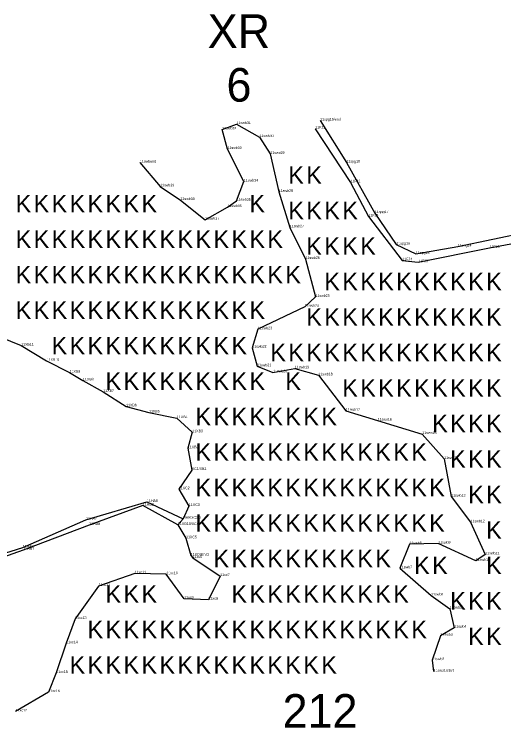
# Model space of a CAD drawing. Extents: x 2072529 to 2268812, y 436423 to 470008.
# Drawn here: x 2230174 to 2231127, y 446771 to 448159 of the extents above; entities that cross this region are included whole.
import ezdxf

# ---------------------------------------------------------------- set-up
doc = ezdxf.new("R2010")
doc.units = 0
for name, color, linetype in [('Old_Level_10', 7, 'Continuous'), ('Old_Level_20', 7, 'Continuous'), ('Old_Level_52', 7, 'Continuous'), ('Old_Level_55', 7, 'Continuous'), ('Old_Level_60', 7, 'Continuous'), ('Old_Level_62', 7, 'Continuous')]:
    doc.layers.add(name, color=color, linetype=linetype)

msp = doc.modelspace()

# ---------------------------------------------------------------- linework, layer by layer
at = {"layer": 'Old_Level_10'}
for points in [[(2230769.394, 447951.882), (2230820.468, 447870.14), (2230875.802, 447771.916), (2230917.643, 447710.638), (2230955.8, 447692.492), (2231037.496, 447706.907), (2231173.407, 447735.498), (2231315.304, 447761.122), (2231455.152, 447786.77), (2231613.245, 447790.272), (2231730.779, 447794.105), (2231802.313, 447822.04), (2231902.637, 447895.433), (2231968.706, 447942.06), (2232060.909, 448002.163), (2232107.899, 448039.336), (2232157.408, 448074.653), (2232140.017, 448092.714), (2232118.49, 448126.789)], [(2230418.674, 447870.165), (2230457.785, 447823.781), (2230497.454, 447797.32), (2230545.291, 447758.924), (2230589.102, 447783.547), (2230606.663, 447795.911), (2230620.955, 447833.276), (2230589.052, 447896.493), (2230578.639, 447934.458), (2230606.793, 447944.95), (2230651.122, 447919.651), (2230672.44, 447886.991), (2230688.884, 447813.012), (2230710.238, 447744.027), (2230740.968, 447682.572), (2230760.414, 447609.03), (2230739.307, 447589.655), (2230648.264, 447546.025), (2230637.297, 447510.087), (2230646.632, 447474.103), (2230677.584, 447462.11), (2230720.249, 447469.884), (2230766.042, 447456.434), (2230819.357, 447387.419), (2230881.339, 447368.316), (2230968.283, 447342.148), (2231010.924, 447293.767), (2231024.565, 447220.494), (2231062.235, 447170.609), (2231090.759, 447108.107), (2231072.339, 447095.635), (2230999.24, 447129.252), (2230943.038, 447127.924), (2230924.582, 447081.203), (2230985.35, 447028.279), (2231021.52, 447002.6), (2231030.311, 446965.581), (2231003.625, 446949.889), (2230987.319, 446902.522), (2230990.319, 446880.292)]]:
    msp.add_lwpolyline(points, dxfattribs=at)
at = {"layer": 'Old_Level_20'}
for p, q in [((2230606.793, 447944.95), (2230606.793, 447944.95)), ((2230769.394, 447951.882), (2230769.394, 447951.882)), ((2230769.394, 447951.882), (2230769.394, 447951.882)), ((2230578.639, 447934.458), (2230578.639, 447934.458)), ((2230759.811, 447936.011), (2230759.811, 447936.011)), ((2230651.122, 447919.651), (2230651.122, 447919.651)), ((2230589.052, 447896.493), (2230589.052, 447896.493)), ((2230672.44, 447886.991), (2230672.44, 447886.991)), ((2230418.674, 447870.165), (2230418.674, 447870.165)), ((2230820.468, 447870.14), (2230820.468, 447870.14)), ((2230820.468, 447870.14), (2230820.468, 447870.14)), ((2230620.955, 447833.276), (2230620.955, 447833.276)), ((2230828.534, 447831.652), (2230828.534, 447831.652)), ((2230457.785, 447823.781), (2230457.785, 447823.781)), ((2230688.884, 447813.012), (2230688.884, 447813.012)), ((2230497.454, 447797.32), (2230497.454, 447797.32)), ((2230606.663, 447795.911), (2230606.663, 447795.911)), ((2230589.102, 447783.547), (2230589.102, 447783.547)), ((2230863.533, 447765.149), (2230863.533, 447765.149)), ((2230875.802, 447771.916), (2230875.802, 447771.916)), ((2230875.802, 447771.916), (2230875.802, 447771.916)), ((2230545.291, 447758.924), (2230545.291, 447758.924)), ((2230710.238, 447744.027), (2230710.238, 447744.027)), ((2230917.643, 447710.638), (2230917.643, 447710.638)), ((2230917.643, 447710.638), (2230917.643, 447710.638)), ((2231037.496, 447706.907), (2231037.496, 447706.907)), ((2231037.496, 447706.907), (2231037.496, 447706.907)), ((2231099.106, 447704.027), (2231099.106, 447704.027)), ((2230955.8, 447692.492), (2230955.8, 447692.492)), ((2230955.8, 447692.492), (2230955.8, 447692.492)), ((2230740.968, 447682.572), (2230740.968, 447682.572)), ((2230929.3, 447679.936), (2230929.3, 447679.936)), ((2230960.246, 447676.326), (2230960.246, 447676.326)), ((2230760.414, 447609.03), (2230760.414, 447609.03)), ((2230739.307, 447589.655), (2230739.307, 447589.655)), ((2230648.264, 447546.025), (2230648.264, 447546.025)), ((2230187.479, 447514.119), (2230187.479, 447514.119)), ((2230637.297, 447510.087), (2230637.297, 447510.087)), ((2230236.995, 447484.617), (2230236.995, 447484.617)), ((2230646.632, 447474.103), (2230646.632, 447474.103)), ((2230720.249, 447469.884), (2230720.249, 447469.884)), ((2230281.831, 447461.598), (2230281.831, 447461.598)), ((2230677.584, 447462.11), (2230677.584, 447462.11)), ((2230766.042, 447456.434), (2230766.042, 447456.434)), ((2230307.705, 447446.476), (2230307.705, 447446.476)), ((2230347.244, 447424.166), (2230347.244, 447424.166)), ((2230391.645, 447396.034), (2230391.645, 447396.034)), ((2230819.357, 447387.419), (2230819.357, 447387.419)), ((2230436.28, 447384.089), (2230436.28, 447384.089)), ((2230490.653, 447373.166), (2230490.653, 447373.166)), ((2230881.339, 447368.316), (2230881.339, 447368.316)), ((2230520.496, 447345.748), (2230520.496, 447345.748)), ((2230968.283, 447342.148), (2230968.283, 447342.148)), ((2230511.824, 447314.745), (2230511.824, 447314.745)), ((2231010.924, 447293.767), (2231010.924, 447293.767)), ((2230519.567, 447272.202), (2230519.567, 447272.202)), ((2230494.218, 447234.889), (2230494.218, 447234.889)), ((2231024.565, 447220.494), (2231024.565, 447220.494)), ((2230432.311, 447210.178), (2230432.311, 447210.178)), ((2230424.391, 447203.105), (2230424.391, 447203.105)), ((2230513.948, 447202.276), (2230513.948, 447202.276)), ((2230502.832, 447177.345), (2230502.832, 447177.345)), ((2230313.663, 447175.511), (2230313.663, 447175.511)), ((2230319.6, 447165.281), (2230319.6, 447165.281)), ((2230492.588, 447165.355), (2230492.588, 447165.355)), ((2231062.235, 447170.609), (2231062.235, 447170.609)), ((2230508.296, 447139.437), (2230508.296, 447139.437)), ((2230190.395, 447121.729), (2230190.395, 447121.729)), ((2230943.038, 447127.924), (2230943.038, 447127.924)), ((2230999.24, 447129.252), (2230999.24, 447129.252)), ((2230191.644, 447116.47), (2230191.644, 447116.47)), ((2231090.759, 447108.107), (2231090.759, 447108.107)), ((2230517.415, 447105.795), (2230517.415, 447105.795)), ((2230521.647, 447101.442), (2230521.647, 447101.442)), ((2231072.339, 447095.635), (2231072.339, 447095.635)), ((2230924.582, 447081.203), (2230924.582, 447081.203)), ((2230408.408, 447071.303), (2230408.408, 447071.303)), ((2230469.973, 447069.696), (2230469.973, 447069.696)), ((2230574.736, 447066.064), (2230574.736, 447066.064)), ((2230338.319, 447046.586), (2230338.319, 447046.586)), ((2230985.35, 447028.279), (2230985.35, 447028.279)), ((2230504.663, 447022.064), (2230504.663, 447022.064)), ((2230551.941, 447020.098), (2230551.941, 447020.098)), ((2231021.52, 447002.6), (2231021.52, 447002.6)), ((2230292.282, 446982.862), (2230292.282, 446982.862)), ((2231030.311, 446965.581), (2231030.311, 446965.581)), ((2231003.625, 446949.889), (2231003.625, 446949.889)), ((2230275.143, 446935.245), (2230275.143, 446935.245)), ((2230987.319, 446902.522), (2230987.319, 446902.522)), ((2230255.83, 446877.586), (2230255.83, 446877.586)), ((2230990.319, 446880.292), (2230990.319, 446880.292)), ((2230240.469, 446840.352), (2230240.469, 446840.352)), ((2230176.496, 446802.681), (2230176.496, 446802.681))]:
    msp.add_line(p, q, dxfattribs=at)
at = {"layer": 'Old_Level_52'}
for points in [[(2230759.811, 447936.011), (2230828.534, 447831.652), (2230863.533, 447765.149), (2230929.3, 447679.936), (2230960.246, 447676.326), (2231099.106, 447704.027), (2231237.511, 447730.295), (2231391.369, 447760.081), (2231546.1, 447771.484), (2231706.131, 447772.616), (2231807.646, 447794.925), (2231974.226, 447918.42)], [(2230145.048, 447531.311), (2230187.479, 447514.119), (2230236.995, 447484.617), (2230281.831, 447461.598), (2230307.705, 447446.476), (2230347.244, 447424.166), (2230391.645, 447396.034), (2230436.28, 447384.089), (2230490.653, 447373.166), (2230520.496, 447345.748), (2230511.824, 447314.745), (2230519.567, 447272.202), (2230494.218, 447234.889), (2230513.948, 447202.276), (2230502.832, 447177.345), (2230492.588, 447165.355), (2230508.296, 447139.437), (2230517.415, 447105.795)], [(2230492.588, 447165.355), (2230424.391, 447203.105), (2230319.6, 447165.281), (2230191.644, 447116.47), (2230068.223, 447073.263), (2229915.312, 447016.898), (2229787.07, 446977.903), (2229665.632, 446932.019), (2229590.567, 446934.149), (2229593.53, 446943.669), (2229665.094, 446950.354), (2229787.213, 446986.774), (2229909.621, 447029.326), (2230066.407, 447082.621), (2230190.395, 447121.729), (2230313.663, 447175.511), (2230432.311, 447210.178), (2230502.832, 447177.345)], [(2230517.415, 447105.795), (2230521.647, 447101.442), (2230574.736, 447066.064), (2230551.941, 447020.098), (2230504.663, 447022.064), (2230469.973, 447069.696), (2230408.408, 447071.303), (2230338.319, 447046.586), (2230292.282, 446982.862), (2230275.143, 446935.245), (2230255.83, 446877.586), (2230240.469, 446840.352), (2230176.496, 446802.681)]]:
    msp.add_lwpolyline(points, dxfattribs=at)

# ---------------------------------------------------------------- texts
at = {"layer": 'Old_Level_55'}
for p in [(2230707.479, 447828.791), (2230742.479, 447828.791), (2230176.739, 447773.184), (2230211.739, 447773.184), (2230246.739, 447773.184), (2230281.739, 447773.184), (2230316.739, 447773.184), (2230351.739, 447773.184), (2230386.739, 447773.184), (2230421.739, 447773.184), (2230631.739, 447773.184), (2230707.479, 447759.791), (2230742.479, 447759.791), (2230777.479, 447759.791), (2230812.479, 447759.791), (2230176.739, 447704.184), (2230211.739, 447704.184), (2230246.739, 447704.184), (2230281.739, 447704.184), (2230316.739, 447704.184), (2230351.739, 447704.184), (2230386.739, 447704.184), (2230421.739, 447704.184), (2230456.739, 447704.184), (2230491.739, 447704.184), (2230526.739, 447704.184), (2230561.739, 447704.184), (2230596.739, 447704.184), (2230631.739, 447704.184), (2230666.739, 447704.184), (2230742.479, 447690.791), (2230777.479, 447690.791), (2230812.479, 447690.791), (2230847.479, 447690.791), (2230176.739, 447635.184), (2230211.739, 447635.184), (2230246.739, 447635.184), (2230281.739, 447635.184), (2230316.739, 447635.184), (2230351.739, 447635.184), (2230386.739, 447635.184), (2230421.739, 447635.184), (2230456.739, 447635.184), (2230491.739, 447635.184), (2230526.739, 447635.184), (2230561.739, 447635.184), (2230596.739, 447635.184), (2230631.739, 447635.184), (2230666.739, 447635.184), (2230701.739, 447635.184), (2230777.479, 447621.791), (2230812.479, 447621.791), (2230847.479, 447621.791), (2230882.479, 447621.791), (2230917.479, 447621.791), (2230952.479, 447621.791), (2230987.479, 447621.791), (2231022.479, 447621.791), (2231057.479, 447621.791), (2231092.479, 447621.791), (2230176.739, 447566.184), (2230211.739, 447566.184), (2230246.739, 447566.184), (2230281.739, 447566.184), (2230316.739, 447566.184), (2230351.739, 447566.184), (2230386.739, 447566.184), (2230421.739, 447566.184), (2230456.739, 447566.184), (2230491.739, 447566.184), (2230526.739, 447566.184), (2230561.739, 447566.184), (2230596.739, 447566.184), (2230631.739, 447566.184), (2230742.479, 447552.791), (2230777.479, 447552.791), (2230812.479, 447552.791), (2230847.479, 447552.791), (2230882.479, 447552.791), (2230917.479, 447552.791), (2230952.479, 447552.791), (2230987.479, 447552.791), (2231022.479, 447552.791), (2231057.479, 447552.791), (2231092.479, 447552.791), (2230246.739, 447497.184), (2230281.739, 447497.184), (2230316.739, 447497.184), (2230351.739, 447497.184), (2230386.739, 447497.184), (2230421.739, 447497.184), (2230456.739, 447497.184), (2230491.739, 447497.184), (2230526.739, 447497.184), (2230561.739, 447497.184), (2230596.739, 447497.184), (2230672.479, 447483.791), (2230707.479, 447483.791), (2230742.479, 447483.791), (2230777.479, 447483.791), (2230812.479, 447483.791), (2230847.479, 447483.791), (2230882.479, 447483.791), (2230917.479, 447483.791), (2230952.479, 447483.791), (2230987.479, 447483.791), (2231022.479, 447483.791), (2231057.479, 447483.791), (2231092.479, 447483.791), (2230351.739, 447428.184), (2230386.739, 447428.184), (2230421.739, 447428.184), (2230456.739, 447428.184), (2230491.739, 447428.184), (2230526.739, 447428.184), (2230561.739, 447428.184), (2230596.739, 447428.184), (2230631.739, 447428.184), (2230701.739, 447428.184), (2230812.479, 447414.791), (2230847.479, 447414.791), (2230882.479, 447414.791), (2230917.479, 447414.791), (2230952.479, 447414.791), (2230987.479, 447414.791), (2231022.479, 447414.791), (2231057.479, 447414.791), (2231092.479, 447414.791), (2230526.739, 447359.184), (2230561.739, 447359.184), (2230596.739, 447359.184), (2230631.739, 447359.184), (2230666.739, 447359.184), (2230701.739, 447359.184), (2230736.739, 447359.184), (2230771.739, 447359.184), (2230987.479, 447345.791), (2231022.479, 447345.791), (2231057.479, 447345.791), (2231092.479, 447345.791), (2230526.739, 447290.184), (2230561.739, 447290.184), (2230596.739, 447290.184), (2230631.739, 447290.184), (2230666.739, 447290.184), (2230701.739, 447290.184), (2230736.739, 447290.184), (2230771.739, 447290.184), (2230806.739, 447290.184), (2230841.739, 447290.184), (2230876.739, 447290.184), (2230911.739, 447290.184), (2230946.739, 447290.184), (2231022.479, 447276.791), (2231057.479, 447276.791), (2231092.479, 447276.791), (2230526.739, 447221.184), (2230561.739, 447221.184), (2230596.739, 447221.184), (2230631.739, 447221.184), (2230666.739, 447221.184), (2230701.739, 447221.184), (2230736.739, 447221.184), (2230771.739, 447221.184), (2230806.739, 447221.184), (2230841.739, 447221.184), (2230876.739, 447221.184), (2230911.739, 447221.184), (2230946.739, 447221.184), (2230981.739, 447221.184), (2231057.479, 447207.791), (2231092.479, 447207.791), (2230526.739, 447152.184), (2230561.739, 447152.184), (2230596.739, 447152.184), (2230631.739, 447152.184), (2230666.739, 447152.184), (2230701.739, 447152.184), (2230736.739, 447152.184), (2230771.739, 447152.184), (2230806.739, 447152.184), (2230841.739, 447152.184), (2230876.739, 447152.184), (2230911.739, 447152.184), (2230946.739, 447152.184), (2230981.739, 447152.184), (2231092.479, 447138.791), (2230561.739, 447083.184), (2230596.739, 447083.184), (2230631.739, 447083.184), (2230666.739, 447083.184), (2230701.739, 447083.184), (2230736.739, 447083.184), (2230771.739, 447083.184), (2230806.739, 447083.184), (2230841.739, 447083.184), (2230876.739, 447083.184), (2230952.479, 447069.791), (2230987.479, 447069.791), (2231092.479, 447069.791), (2230351.739, 447014.184), (2230386.739, 447014.184), (2230421.739, 447014.184), (2230596.739, 447014.184), (2230631.739, 447014.184), (2230666.739, 447014.184), (2230701.739, 447014.184), (2230736.739, 447014.184), (2230771.739, 447014.184), (2230806.739, 447014.184), (2230841.739, 447014.184), (2230876.739, 447014.184), (2230911.739, 447014.184), (2231022.479, 447000.791), (2231057.479, 447000.791), (2231092.479, 447000.791), (2230316.739, 446945.184), (2230351.739, 446945.184), (2230386.739, 446945.184), (2230421.739, 446945.184), (2230456.739, 446945.184), (2230491.739, 446945.184), (2230526.739, 446945.184), (2230561.739, 446945.184), (2230596.739, 446945.184), (2230631.739, 446945.184), (2230666.739, 446945.184), (2230701.739, 446945.184), (2230736.739, 446945.184), (2230771.739, 446945.184), (2230806.739, 446945.184), (2230841.739, 446945.184), (2230876.739, 446945.184), (2230911.739, 446945.184), (2230946.739, 446945.184), (2231057.479, 446931.791), (2231092.479, 446931.791), (2230281.739, 446876.184), (2230316.739, 446876.184), (2230351.739, 446876.184), (2230386.739, 446876.184), (2230421.739, 446876.184), (2230456.739, 446876.184), (2230491.739, 446876.184), (2230526.739, 446876.184), (2230561.739, 446876.184), (2230596.739, 446876.184), (2230631.739, 446876.184), (2230666.739, 446876.184), (2230701.739, 446876.184), (2230736.739, 446876.184), (2230771.739, 446876.184)]:
    msp.add_text('K', height=34, dxfattribs=at).set_placement(p)
at = {"layer": 'Old_Level_60'}
for s, p in [('11spg19/end', (2230769.394, 447951.882)), ('11spg19/end', (2230769.394, 447951.882)), ('11swb31', (2230606.793, 447944.95)), ('11FJ1', (2230759.811, 447936.011)), ('11swb32', (2230578.639, 447934.458)), ('11swb30', (2230651.122, 447919.651)), ('11swb33', (2230589.052, 447896.493)), ('11swb29', (2230672.44, 447886.991)), ('11swbend', (2230418.674, 447870.165)), ('11spg18', (2230820.468, 447870.14)), ('11spg18', (2230820.468, 447870.14)), ('11swb39', (2230457.785, 447823.781)), ('11swb34', (2230620.955, 447833.276)), ('11FJ2', (2230828.534, 447831.652)), ('11swb28', (2230688.884, 447813.012)), ('11swb38', (2230497.454, 447797.32)), ('11swb35', (2230606.663, 447795.911)), ('11swb36', (2230589.102, 447783.547)), ('11spg17', (2230875.802, 447771.916)), ('11spg17', (2230875.802, 447771.916)), ('11swb37', (2230545.291, 447758.924)), ('11FJ3', (2230863.533, 447765.149)), ('11swb27', (2230710.238, 447744.027)), ('11spg16', (2230917.643, 447710.638)), ('11spg16', (2230917.643, 447710.638)), ('11spg14', (2231037.496, 447706.907)), ('11spg14', (2231037.496, 447706.907)), ('11FJ6', (2231099.106, 447704.027)), ('11spg15', (2230955.8, 447692.492)), ('11spg15', (2230955.8, 447692.492)), ('11swb26', (2230740.968, 447682.572)), ('11FJ4', (2230929.3, 447679.936)), ('11FJ5', (2230960.246, 447676.326)), ('11swb25', (2230760.414, 447609.03)), ('11swb24', (2230739.307, 447589.655)), ('11swb23', (2230648.264, 447546.025)), ('11XB11', (2230187.479, 447514.119)), ('11swb22', (2230637.297, 447510.087)), ('11XB10', (2230236.995, 447484.617)), ('11swb21', (2230646.632, 447474.103)), ('11swb19', (2230720.249, 447469.884)), ('11XB9', (2230281.831, 447461.598)), ('11swb20', (2230677.584, 447462.11)), ('11swb18', (2230766.042, 447456.434)), ('11XB8', (2230307.705, 447446.476)), ('11XB7', (2230347.244, 447424.166)), ('11XB6', (2230391.645, 447396.034)), ('11XB5', (2230436.28, 447384.089)), ('11swb17', (2230819.357, 447387.419)), ('11XB4', (2230490.653, 447373.166)), ('11swb16', (2230881.339, 447368.316)), ('11XB3', (2230520.496, 447345.748)), ('11swb15', (2230968.283, 447342.148)), ('11XB2', (2230511.824, 447314.745)), ('11swb14', (2231010.924, 447293.767)), ('XC1/XB1', (2230519.567, 447272.202)), ('11XC2', (2230494.218, 447234.889)), ('11swb13', (2231024.565, 447220.494)), ('11HB9', (2230424.391, 447203.105)), ('11HA8', (2230432.311, 447210.178)), ('11XC3', (2230513.948, 447202.276)), ('11HA7', (2230313.663, 447175.511)), ('HA9/XC3.5', (2230502.832, 447177.345)), ('11HB8', (2230319.6, 447165.281)), ('11HB10/XC4', (2230492.588, 447165.355)), ('11swb12', (2231062.235, 447170.609)), ('11XC5', (2230508.296, 447139.437)), ('11HA6', (2230190.395, 447121.729)), ('11HB7', (2230191.644, 447116.47)), ('11swb8', (2230943.038, 447127.924)), ('11swb9', (2230999.24, 447129.252)), ('11XC6END', (2230517.415, 447105.795)), ('11swb11', (2231090.759, 447108.107)), ('11xc6', (2230521.647, 447101.442)), ('11swb10', (2231072.339, 447095.635)), ('11swb7', (2230924.582, 447081.203)), ('11xc11', (2230408.408, 447071.303)), ('11xc10', (2230469.973, 447069.696)), ('11xc7', (2230574.736, 447066.064)), ('11xc12', (2230338.319, 447046.586)), ('11xc9', (2230504.663, 447022.064)), ('11xc8', (2230551.941, 447020.098)), ('11swb6', (2230985.35, 447028.279)), ('11swb5', (2231021.52, 447002.6)), ('11xc13', (2230292.282, 446982.862)), ('11swb4', (2231030.311, 446965.581)), ('11swb3', (2231003.625, 446949.889)), ('11xc14', (2230275.143, 446935.245)), ('11swb2', (2230987.319, 446902.522)), ('11swb1/start', (2230990.319, 446880.292)), ('11xc15', (2230255.83, 446877.586)), ('11xc16', (2230240.469, 446840.352)), ('11xc17', (2230176.496, 446802.681))]:
    msp.add_text(s, height=5, dxfattribs=at).set_placement(p)
at = {"layer": 'Old_Level_62'}
for s, p in [('XR', (2230550.61, 448093.175)), ('6', (2230587.116, 447988.631)), ('212', (2230696.353, 446771.103))]:
    msp.add_text(s, height=65.34, dxfattribs=at).set_placement(p)

doc.saveas('drawing.dxf')
